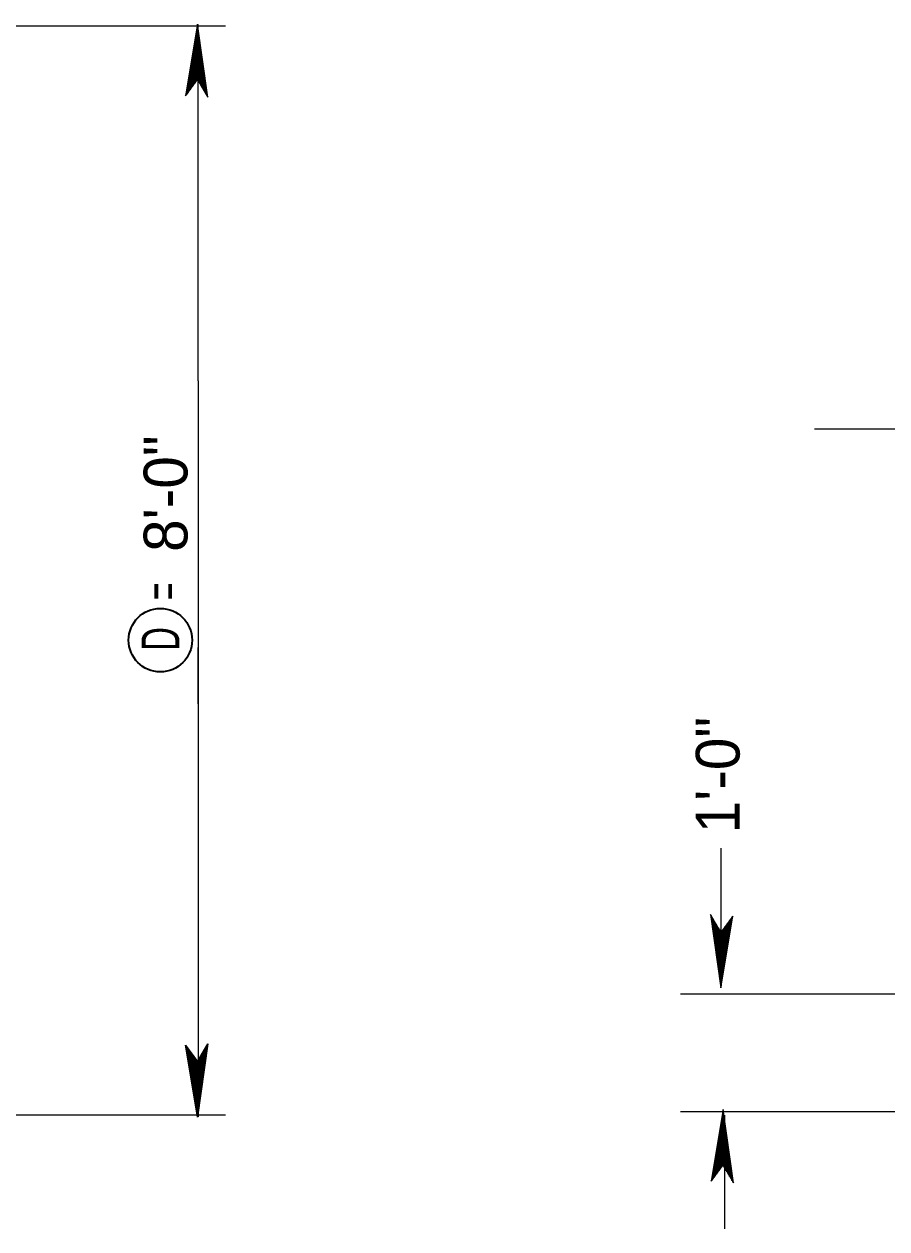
# Model space of a CAD drawing. Extents: x 144 to 252, y 360 to 425.
# Drawn here: x 182.91 to 189.37, y 391.53 to 400.56 of the extents above; entities that cross this region are included whole.
import ezdxf
from ezdxf.enums import TextEntityAlignment as Align

# ---------------------------------------------------------------- set-up
doc = ezdxf.new("R2010")
doc.units = 0
doc.header["$LTSCALE"] = 0.13
for name, color, linetype, lineweight in [('1', 7, 'Continuous', 40), ('16', 7, 'Continuous', 13), ('3', 7, 'Continuous', 13)]:
    doc.layers.add(name, color=color, linetype=linetype, lineweight=lineweight)

msp = doc.modelspace()

# ---------------------------------------------------------------- linework, layer by layer
at = {"layer": '1', "lineweight": 13}
for p, q in [((184.4158, 400.5411), (182.4244, 400.5411)), ((184.2104, 397.8819), (184.2104, 400.5526)), ((184.2104, 397.8819), (184.2104, 392.3664)), ((184.2104, 395.4595), (184.2104, 395.8819)), ((184.4158, 392.3779), (182.4244, 392.3779))]:
    msp.add_line(p, q, dxfattribs=at)
at = {"layer": '1', "lineweight": 35}
msp.add_circle((183.9278, 395.9379), 0.238, dxfattribs=at)
at = {"layer": '3'}
for p, q in [((184.2063, 400.5554), (184.1171, 400.0177)), ((184.2057, 400.541), (184.1194, 400.021)), ((184.2057, 400.5302), (184.1217, 400.0242)), ((184.2057, 400.5157), (184.1249, 400.0285)), ((184.2057, 400.503), (184.1276, 400.0322)), ((184.2057, 400.4917), (184.13, 400.0356)), ((184.2806, 400.0127), (184.2057, 400.541)), ((184.2786, 400.0162), (184.2057, 400.5302)), ((184.2759, 400.0207), (184.2057, 400.5157)), ((184.2735, 400.0248), (184.2057, 400.503)), ((184.2735, 400.0248), (184.2057, 400.503)), ((184.2713, 400.0285), (184.2057, 400.4917)), ((184.2063, 400.14), (184.2063, 400.5554)), ((184.2841, 400.0067), (184.2063, 400.5554)), ((184.2057, 400.4772), (184.1332, 400.0398)), ((184.2057, 400.4645), (184.1359, 400.0436)), ((184.2057, 400.4507), (184.1388, 400.0477)), ((184.2057, 400.4369), (184.1418, 400.0517)), ((184.2057, 400.4237), (184.1447, 400.0557)), ((184.2057, 400.4097), (184.1477, 400.0598)), ((184.2687, 400.0331), (184.2057, 400.4772)), ((184.2662, 400.0372), (184.2057, 400.4645)), ((184.2637, 400.0416), (184.2057, 400.4507)), ((184.2612, 400.046), (184.2057, 400.4369)), ((184.2587, 400.0503), (184.2057, 400.4237)), ((184.256, 400.0548), (184.2057, 400.4097)), ((184.2057, 400.3972), (184.1503, 400.0635)), ((184.2057, 400.3857), (184.1528, 400.0669)), ((184.2057, 400.3701), (184.1562, 400.0715)), ((184.2057, 400.3562), (184.1592, 400.0756)), ((184.2052, 400.3382), (184.1623, 400.0798)), ((184.2052, 400.3243), (184.1652, 400.084)), ((184.2052, 400.3112), (184.1681, 400.0878)), ((184.2418, 400.0791), (184.2052, 400.3382)), ((184.2392, 400.0835), (184.2052, 400.3243)), ((184.2368, 400.0877), (184.2052, 400.3112)), ((184.2537, 400.0587), (184.2057, 400.3972)), ((184.2515, 400.0625), (184.2057, 400.3857)), ((184.2487, 400.0675), (184.2057, 400.3701)), ((184.246, 400.0719), (184.2057, 400.3562)), ((184.2438, 400.0759), (184.2067, 400.3367)), ((184.2057, 400.3021), (184.1708, 400.0916)), ((184.2057, 400.2901), (184.1734, 400.0952)), ((184.2057, 400.2763), (184.1764, 400.0992)), ((184.2057, 400.2606), (184.1797, 400.1039)), ((184.2057, 400.248), (184.1824, 400.1076)), ((184.2057, 400.2347), (184.1852, 400.1115)), ((184.2057, 400.2227), (184.1879, 400.1151)), ((184.2359, 400.0892), (184.2057, 400.3021)), ((184.2337, 400.0932), (184.2057, 400.2901)), ((184.231, 400.0976), (184.2057, 400.2763)), ((184.2282, 400.1026), (184.2057, 400.2606)), ((184.2258, 400.1067), (184.2057, 400.248)), ((184.2233, 400.1109), (184.2057, 400.2347)), ((184.221, 400.1148), (184.2057, 400.2227)), ((184.1171, 400.0177), (184.2062, 400.1402)), ((184.2057, 400.2082), (184.1909, 400.1193)), ((184.2057, 400.1944), (184.1939, 400.1235)), ((184.2057, 400.1817), (184.1967, 400.1272)), ((184.2057, 400.1685), (184.1995, 400.1311)), ((184.2057, 400.1571), (184.2019, 400.1345)), ((184.2057, 400.1469), (184.2042, 400.1375)), ((184.2183, 400.1194), (184.2057, 400.2082)), ((184.2157, 400.1238), (184.2057, 400.1944)), ((184.2134, 400.1279), (184.2057, 400.1817)), ((184.2087, 400.1358), (184.2057, 400.1571)), ((184.2062, 400.1402), (184.2841, 400.0067)), ((184.2103, 400.1332), (184.2067, 400.1583)), ((188.8303, 397.5218), (190.05, 397.5218)), ((188.1284, 394.3788), (188.1284, 393.5257)), ((188.0517, 393.881), (188.1295, 393.3322)), ((188.1297, 393.7474), (188.0517, 393.881)), ((188.0553, 393.875), (188.1302, 393.3467)), ((188.0572, 393.8715), (188.1302, 393.3575)), ((188.0599, 393.8669), (188.1302, 393.3719)), ((188.0623, 393.8628), (188.1302, 393.3847)), ((188.0623, 393.8628), (188.1302, 393.3847)), ((188.0645, 393.8592), (188.1302, 393.396)), ((188.0672, 393.8546), (188.1302, 393.4104)), ((188.0696, 393.8505), (188.1302, 393.4232)), ((188.0721, 393.8461), (188.1302, 393.4369)), ((188.0747, 393.8417), (188.1302, 393.4507)), ((188.0772, 393.8374), (188.1302, 393.464)), ((188.0798, 393.8329), (188.1302, 393.4779)), ((188.0821, 393.8289), (188.1302, 393.4905)), ((188.0843, 393.8252), (188.1302, 393.5019)), ((188.0872, 393.8202), (188.1302, 393.5176)), ((188.0898, 393.8157), (188.1302, 393.5314)), ((188.0921, 393.8117), (188.1291, 393.551)), ((188.094, 393.8086), (188.1307, 393.5494)), ((188.1295, 393.3322), (188.2188, 393.8699)), ((188.2188, 393.8699), (188.1297, 393.7474)), ((188.1302, 393.3467), (188.2164, 393.8667)), ((188.1302, 393.3575), (188.2141, 393.8634)), ((188.1302, 393.3719), (188.2109, 393.8592)), ((188.1302, 393.3847), (188.2082, 393.8554)), ((188.1302, 393.396), (188.2058, 393.8521)), ((188.1302, 393.4104), (188.2027, 393.8478)), ((188.1302, 393.4232), (188.1999, 393.8441)), ((188.1302, 393.4369), (188.197, 393.84)), ((188.1302, 393.4507), (188.194, 393.8359)), ((188.1302, 393.464), (188.1912, 393.832)), ((188.1302, 393.4779), (188.1882, 393.8279)), ((188.1302, 393.4905), (188.1855, 393.8242)), ((188.1302, 393.5019), (188.183, 393.8207)), ((188.1302, 393.5176), (188.1797, 393.8162)), ((188.1302, 393.5314), (188.1767, 393.8121)), ((188.1307, 393.5494), (188.1736, 393.8078)), ((188.0966, 393.8042), (188.1307, 393.5633)), ((188.0991, 393.7999), (188.1307, 393.5765)), ((188.0999, 393.7984), (188.1302, 393.5856)), ((188.1022, 393.7945), (188.1302, 393.5976)), ((188.1048, 393.7901), (188.1302, 393.6114)), ((188.1077, 393.7851), (188.1302, 393.6271)), ((188.1101, 393.781), (188.1302, 393.6397)), ((188.1126, 393.7767), (188.1302, 393.6529)), ((188.1148, 393.7729), (188.1302, 393.6649)), ((188.1175, 393.7682), (188.1302, 393.6794)), ((188.1201, 393.7638), (188.1302, 393.6932)), ((188.1224, 393.7597), (188.1302, 393.7059)), ((188.1255, 393.7545), (188.1291, 393.7294)), ((188.1271, 393.7518), (188.1302, 393.7306)), ((188.1295, 393.7477), (188.1295, 393.3322)), ((188.1302, 393.5856), (188.165, 393.7961)), ((188.1302, 393.5976), (188.1624, 393.7925)), ((188.1302, 393.6114), (188.1594, 393.7884)), ((188.1302, 393.6271), (188.1562, 393.7837)), ((188.1302, 393.6397), (188.1534, 393.7801)), ((188.1302, 393.6529), (188.1506, 393.7762)), ((188.1302, 393.6649), (188.1479, 393.7726)), ((188.1302, 393.6794), (188.1449, 393.7683)), ((188.1302, 393.6932), (188.1419, 393.7642)), ((188.1302, 393.7059), (188.1392, 393.7605)), ((188.1302, 393.7192), (188.1363, 393.7566)), ((188.1302, 393.7306), (188.1339, 393.7532)), ((188.1302, 393.7407), (188.1317, 393.7502)), ((188.1307, 393.5633), (188.1706, 393.8037)), ((188.1307, 393.5765), (188.1677, 393.7998)), ((190.9256, 393.2852), (187.8267, 393.2852)), ((184.2806, 392.9063), (184.2057, 392.378)), ((184.2062, 392.7788), (184.2841, 392.9123)), ((184.2841, 392.9123), (184.2063, 392.3636)), ((184.2063, 392.3636), (184.1171, 392.9013)), ((184.1171, 392.9013), (184.2062, 392.7788)), ((184.2057, 392.378), (184.1194, 392.898)), ((184.2057, 392.3888), (184.1217, 392.8947)), ((184.2057, 392.4033), (184.1249, 392.8905)), ((184.2057, 392.416), (184.1276, 392.8868)), ((184.2057, 392.4273), (184.13, 392.8834)), ((184.2057, 392.4418), (184.1332, 392.8792)), ((184.2057, 392.4545), (184.1359, 392.8754)), ((184.2057, 392.4683), (184.1388, 392.8713)), ((184.2057, 392.4821), (184.1418, 392.8673)), ((184.2057, 392.4953), (184.1447, 392.8633)), ((184.2057, 392.5093), (184.1477, 392.8592)), ((184.2057, 392.5218), (184.1503, 392.8555)), ((184.2057, 392.5333), (184.1528, 392.8521)), ((184.2057, 392.5489), (184.1562, 392.8475)), ((184.2057, 392.5627), (184.1592, 392.8434)), ((184.2052, 392.5807), (184.1623, 392.8392)), ((184.2052, 392.5947), (184.1652, 392.835)), ((184.2052, 392.6078), (184.1681, 392.8312)), ((184.2057, 392.6169), (184.1708, 392.8274)), ((184.2057, 392.6289), (184.1734, 392.8238)), ((184.2057, 392.6427), (184.1764, 392.8197)), ((184.2057, 392.6584), (184.1797, 392.8151)), ((184.2418, 392.8399), (184.2052, 392.5807)), ((184.2392, 392.8355), (184.2052, 392.5947)), ((184.2368, 392.8313), (184.2052, 392.6078)), ((184.2786, 392.9028), (184.2057, 392.3888)), ((184.2759, 392.8982), (184.2057, 392.4033)), ((184.2735, 392.8942), (184.2057, 392.416)), ((184.2735, 392.8942), (184.2057, 392.416)), ((184.2713, 392.8905), (184.2057, 392.4273)), ((184.2687, 392.8859), (184.2057, 392.4418)), ((184.2662, 392.8818), (184.2057, 392.4545)), ((184.2637, 392.8774), (184.2057, 392.4683)), ((184.2612, 392.873), (184.2057, 392.4821)), ((184.2587, 392.8687), (184.2057, 392.4953)), ((184.256, 392.8642), (184.2057, 392.5093)), ((184.2537, 392.8603), (184.2057, 392.5218)), ((184.2515, 392.8565), (184.2057, 392.5333)), ((184.2487, 392.8515), (184.2057, 392.5489)), ((184.246, 392.8471), (184.2057, 392.5627)), ((184.2359, 392.8297), (184.2057, 392.6169)), ((184.2337, 392.8258), (184.2057, 392.6289)), ((184.231, 392.8214), (184.2057, 392.6427)), ((184.2282, 392.8164), (184.2057, 392.6584)), ((184.2438, 392.8431), (184.2067, 392.5823)), ((184.2057, 392.671), (184.1824, 392.8114)), ((184.2057, 392.6842), (184.1852, 392.8075)), ((184.2057, 392.6962), (184.1879, 392.8039)), ((184.2057, 392.7107), (184.1909, 392.7997)), ((184.2057, 392.7246), (184.1939, 392.7955)), ((184.2057, 392.7372), (184.1967, 392.7918)), ((184.2057, 392.7505), (184.1995, 392.7879)), ((184.2057, 392.7619), (184.2019, 392.7845)), ((184.2057, 392.7721), (184.2042, 392.7815)), ((184.2258, 392.8123), (184.2057, 392.671)), ((184.2233, 392.8081), (184.2057, 392.6842)), ((184.221, 392.8042), (184.2057, 392.6962)), ((184.2183, 392.7996), (184.2057, 392.7107)), ((184.2157, 392.7952), (184.2057, 392.7246)), ((184.2134, 392.7911), (184.2057, 392.7372)), ((184.2087, 392.7832), (184.2057, 392.7619)), ((184.2063, 392.779), (184.2063, 392.3636)), ((184.2103, 392.7858), (184.2067, 392.7607)), ((189.6495, 392.4032), (187.8267, 392.4032)), ((188.1453, 392.4194), (188.056, 391.8818)), ((188.1446, 392.405), (188.0583, 391.885)), ((188.1446, 392.3942), (188.0607, 391.8882)), ((188.1446, 392.3798), (188.0638, 391.8925)), ((188.1446, 392.367), (188.0665, 391.8963)), ((188.2195, 391.8767), (188.1446, 392.405)), ((188.2175, 391.8802), (188.1446, 392.3942)), ((188.2148, 391.8847), (188.1446, 392.3798)), ((188.2124, 391.8888), (188.1446, 392.367)), ((188.2124, 391.8888), (188.1446, 392.367)), ((188.1453, 392.004), (188.1453, 392.4194)), ((188.223, 391.8707), (188.1453, 392.4194)), ((188.1557, 392.3783), (188.1557, 391.5252)), ((188.1446, 392.3557), (188.0689, 391.8996)), ((188.1446, 392.3413), (188.0721, 391.9038)), ((188.1446, 392.3285), (188.0748, 391.9076)), ((188.1446, 392.3148), (188.0777, 391.9117)), ((188.1446, 392.3009), (188.0807, 391.9158)), ((188.1446, 392.2877), (188.0836, 391.9197)), ((188.1446, 392.2738), (188.0866, 391.9237)), ((188.2103, 391.8925), (188.1446, 392.3557)), ((188.2076, 391.8971), (188.1446, 392.3413)), ((188.2052, 391.9012), (188.1446, 392.3285)), ((188.2027, 391.9056), (188.1446, 392.3148)), ((188.2001, 391.91), (188.1446, 392.3009)), ((188.1976, 391.9142), (188.1446, 392.2877)), ((188.1949, 391.9187), (188.1446, 392.2738)), ((188.1446, 392.2612), (188.0892, 391.9275)), ((188.1446, 392.2498), (188.0917, 391.9309)), ((188.1446, 392.2341), (188.0951, 391.9355)), ((188.1446, 392.2202), (188.0981, 391.9396)), ((188.1441, 392.2022), (188.1012, 391.9438)), ((188.1441, 392.1883), (188.1042, 391.948)), ((188.1807, 391.9431), (188.1441, 392.2022)), ((188.1782, 391.9475), (188.1441, 392.1883)), ((188.1927, 391.9228), (188.1446, 392.2612)), ((188.1904, 391.9265), (188.1446, 392.2498)), ((188.1876, 391.9315), (188.1446, 392.2341)), ((188.1849, 391.9359), (188.1446, 392.2202)), ((188.1827, 391.9399), (188.1457, 392.2007)), ((188.1441, 392.1752), (188.107, 391.9518)), ((188.1446, 392.1661), (188.1097, 391.9556)), ((188.1446, 392.1541), (188.1123, 391.9592)), ((188.1446, 392.1402), (188.1153, 391.9632)), ((188.1446, 392.1246), (188.1186, 391.9679)), ((188.1446, 392.112), (188.1213, 391.9716)), ((188.1446, 392.0987), (188.1242, 391.9755)), ((188.1757, 391.9518), (188.1441, 392.1752)), ((188.1748, 391.9532), (188.1446, 392.1661)), ((188.1726, 391.9572), (188.1446, 392.1541)), ((188.1699, 391.9616), (188.1446, 392.1402)), ((188.1671, 391.9666), (188.1446, 392.1246)), ((188.1647, 391.9707), (188.1446, 392.112)), ((188.1622, 391.9749), (188.1446, 392.0987)), ((188.056, 391.8818), (188.1451, 392.0043)), ((188.1446, 392.0867), (188.1268, 391.9791)), ((188.1446, 392.0722), (188.1298, 391.9833)), ((188.1446, 392.0584), (188.1328, 391.9875)), ((188.1446, 392.0457), (188.1356, 391.9912)), ((188.1446, 392.0325), (188.1384, 391.9951)), ((188.1446, 392.0211), (188.1408, 391.9985)), ((188.1446, 392.0109), (188.1431, 392.0015)), ((188.1599, 391.9787), (188.1446, 392.0867)), ((188.1573, 391.9834), (188.1446, 392.0722)), ((188.1547, 391.9878), (188.1446, 392.0584)), ((188.1523, 391.9919), (188.1446, 392.0457)), ((188.1477, 391.9998), (188.1446, 392.0211)), ((188.1451, 392.0043), (188.223, 391.8707)), ((188.1492, 391.9972), (188.1457, 392.0222))]:
    msp.add_line(p, q, dxfattribs=at)

# ---------------------------------------------------------------- texts
at = {"layer": '1'}
for s, width, p in [('=', 0.6, (184.0851, 396.3034)), ('D', 0.65, (184.0697, 395.9467))]:
    msp.add_text(s, height=0.2833, rotation=90, dxfattribs=dict(at, width=width)).set_placement(p, align=Align.CENTER)
at = {"layer": '16'}
msp.add_text('8\'-0"', height=0.3281, rotation=90, dxfattribs=at).set_placement((184.1306, 397.0361), align=Align.CENTER)
msp.add_text('1\'-0"', height=0.3281, rotation=90, dxfattribs=at).set_placement((188.2693, 394.4895))

doc.saveas('drawing.dxf')
